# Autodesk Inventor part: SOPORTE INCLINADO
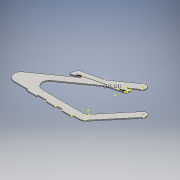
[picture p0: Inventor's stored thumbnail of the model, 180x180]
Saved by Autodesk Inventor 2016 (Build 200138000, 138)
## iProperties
Created: 2016-06
Part Number: SOPORTE INCLINADO
Material: Genérico
Document SubType Name: Modeling
Designer: adm
Density: 1 g/cm^3
Appearance: Valor por defecto
Author: adm
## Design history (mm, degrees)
sketch "Boceto1"
  geometry: L1 (45.284, -220.263)-(201.715, -33.835); L2 (26.631, -180.263)-(171.073, -8.123); L3 (3.65, -190.979)-(-234.496, -190.979); L4 (55.109, 102.688)-(-257.583, -118.314); L5 (32.022, 135.353)-(-383.482, -158.314); L6 (-269.73, -230.979)-(-269.73, -233.979); L7 (-229.73, -230.979)-(-229.73, -233.979); L8 (-159.73, -230.979)-(-159.73, -233.979); L9 (-119.73, -230.979)-(-119.73, -233.979); L10 (-49.73, -230.979)-(-49.73, -233.979); L11 (-40.276, -230.979)-(-40.276, -233.979); L12 (-49.73, -233.979)-(-40.276, -233.979); L13 (-269.73, -233.979)-(-229.73, -233.979); L14 (-159.73, -233.979)-(-119.73, -233.979); L15 (22.302, -230.979)-(-40.276, -230.979); L16 (-49.73, -230.979)-(-119.73, -230.979); L17 (-159.73, -230.979)-(-229.73, -230.979); L18 (-269.73, -230.979)-(-360.395, -230.979); C1 r 3.25 at (186.394, -20.979); C2 r 3.25 at (43.566, 119.021); A1 r 30 centre (22.302, -200.979) between (22.302, -230.979) and (45.284, -220.263); A2 r 20 centre (186.394, -20.979) between (201.715, -33.835) and (171.073, -8.123); A3 r 30 centre (3.65, -160.979) between (3.65, -190.979) and (26.631, -180.263); A4 r 20 centre (43.566, 119.021) between (55.109, 102.688) and (32.022, 135.353); A5 r 40 centre (-234.496, -150.979) between (-257.583, -118.314) and (-234.496, -190.979); A6 r 40 centre (-360.395, -190.979) between (-383.482, -158.314) and (-360.395, -230.979); 3 further points
  constraints: 36 end point, 15 tangent, 13 point on circle, 8 centre point, 3 coincident, 3 horizontal, 3 horizontal alignment, 1 point on line
  dimensions: "d3" = 40 radius of A6; "d5" = 40 radius of A5; "d6" = 30 radius of A3; "d7" = 30 radius of A1; "d20" = 6.5 diameter of C2; "d21" = 6.5 diameter of C1; "d38" = 210 distance from line of C1.centre L15; "d39" = 40 distance between parallel lines of L16 L3; "d40" = 40 distance between parallel lines of L2 L1; "d41" = 40 distance between parallel lines of L5 L4; "d42" = 62.57873 distance of L15.start L11.start; "d43" = 3 distance of L10.start L10.end; "d44" = 3 distance of L11.start L11.end; "d45" = 238.14615 distance of L3.start L3.end; "d46" = 20 radius of A2; "d47" = 350 distance from line of C2.centre L16; "d48" = 20 radius of A4; "d49" = 130 deg angle of L3 L2; "d51" = 200 distance of A4.centre C1.centre
extrude "Extrusión1" new body sketch "Boceto1" distance "d18" = 6; taper "d19" = 0 deg
sketch "Boceto4" dims "d92" = 86
  geometry: L1 (-201.715, -33.835)-(-45.284, -220.263) reference; L2 (-22.302, -230.979)-(40.276, -230.979) reference; L3 (40.276, -230.979)-(40.276, -233.979) reference; L4 (40.276, -233.979)-(49.73, -233.979) reference; L5 (49.73, -233.979)-(49.73, -230.979) reference; L6 (49.73, -230.979)-(119.73, -230.979) reference; L7 (119.73, -230.979)-(119.73, -233.979) reference; L8 (119.73, -233.979)-(159.73, -233.979) reference; L9 (159.73, -233.979)-(159.73, -230.979) reference; L10 (159.73, -230.979)-(229.73, -230.979) reference; L11 (229.73, -230.979)-(229.73, -233.979) reference; L12 (229.73, -233.979)-(269.73, -233.979) reference; L13 (269.73, -233.979)-(269.73, -230.979) reference; L14 (269.73, -230.979)-(360.395, -230.979) reference; L15 (383.482, -158.314)-(-32.022, 135.353) reference; L16 (-55.109, 102.688)-(257.583, -118.314) reference; L17 (234.496, -190.979)-(-3.65, -190.979) reference; L18 (-26.631, -180.263)-(-171.073, -8.123) reference; L19 (-43.566, 119.021)-(-186.394, -20.979); L20 (-13.466, 88.313)-(-115.139, -11.347); L21 (-27.743, 64.115)-(-26.532, 42.84); L22 (-22.812, 38.289)-(233.224, -29.065); L23 (239.266, -22.731)-(228.5, 11.547); L24 (-16.933, 39.845)-(10.145, 32.721); L25 (10.145, 32.721)-(11.724, 38.721); L26 (11.724, 38.721)-(-15.355, 45.845); L27 (-15.355, 45.845)-(-16.933, 39.845); L28 (183.373, -12.849)-(210.451, -19.972); L29 (210.451, -19.972)-(211.978, -14.169); L30 (211.978, -14.169)-(184.899, -7.046); L31 (184.899, -7.046)-(183.373, -12.849); L32 (-22.169, 69.365)-(226.174, 14.411); C1 r 3.25 at (-43.566, 119.021); C2 r 8 at (-43.566, 119.021); C3 r 3.25 at (-43.566, 119.021); C4 r 3.25 at (-43.566, 119.021) reference; C5 r 3.25 at (-186.394, -20.979) reference; C6 r 3.25 at (-43.566, 119.021) reference; C7 r 3.25 at (-186.394, -20.979) reference; A1 r 20 centre (-43.566, 119.021) between (-32.022, 102.688) and (-55.109, 135.353); A2 r 30 centre (-22.302, -200.979) between (-45.284, -220.263) and (-22.302, -230.979) reference; A3 r 40 centre (360.395, -190.979) between (360.395, -230.979) and (383.482, -158.314) reference; A4 r 20 centre (-43.566, 119.021) between (-32.022, 135.353) and (-55.109, 102.688) reference; A5 r 40 centre (234.496, -150.979) between (234.496, -190.979) and (257.583, -118.314) reference; A6 r 30 centre (-3.65, -160.979) between (-26.631, -180.263) and (-3.65, -190.979) reference; A7 r 20 centre (-186.394, -20.979) between (-171.073, -8.123) and (-201.715, -33.835) reference; A8 r 5 centre (-22.751, 64.399) between (-22.169, 69.365) and (-27.743, 64.115); A9 r 5 centre (-21.54, 43.125) between (-26.532, 42.84) and (-22.812, 38.289); A10 r 5 centre (234.496, -24.229) between (233.224, -29.065) and (239.266, -22.731); A11 r 5 centre (223.73, 10.049) between (228.5, 11.547) and (226.174, 14.411); 3 further points
  constraints: 28 end point, 10 point on circle, 8 centre point, 6 tangent, 5 coincident, 5 parallel, 3 equal radius, 2 perpendicular, 4 other
  dimensions: "d91" = 16 diameter of C2; "d112" = 57.8254 deg angle of L22 L23; "d113" = 90 deg angle of L25 L24; "d114" = 6 vertical distance of L26.end L24.start; "d115" = 90 deg angle of L28 L31; "d116" = 6 distance of L30.end L28.start; "d118" = 28 distance of L29.end L30.end; "d119" = 28 distance of L25.end L26.end; "d120" = 3 distance between parallel lines of L22 L28; "d121" = 3 distance between parallel lines of L22 L24; "d122" = 5 radius of A8
extrude "Extrusión4" join sketch "Boceto4" distance "d123" = 6; taper "d124" = 0 deg
sketch "Boceto5"
  geometry: L1 (40.276, -230.979)-(-22.302, -230.979) reference; L2 (15.003, -230.979)-(75.003, -230.979); L3 (75.003, -230.979)-(75.003, -238.979); L4 (75.003, -238.979)-(15.003, -238.979); L5 (15.003, -238.979)-(15.003, -230.979); L6 (109.73, -230.979)-(169.73, -230.979); L7 (169.73, -230.979)-(169.73, -238.979); L8 (169.73, -238.979)-(109.73, -238.979); L9 (109.73, -238.979)-(109.73, -230.979); L10 (229.73, -230.979)-(159.73, -230.979) reference; L11 (219.73, -230.979)-(279.73, -230.979); L12 (279.73, -230.979)-(279.73, -238.979); L13 (279.73, -238.979)-(219.73, -238.979); L14 (219.73, -238.979)-(219.73, -230.979); L15 (229.73, -233.979)-(269.73, -233.979) reference; L16 (119.73, -233.979)-(159.73, -233.979) reference; L17 (40.276, -233.979)-(49.73, -233.979) reference; 7 further points
  constraints: 24 end point, 6 midpoint, 6 parallel, 3 horizontal, 3 perpendicular, 3 vertical alignment, 2 point on line, 1 horizontal alignment
  dimensions: "d125" = 8 distance of L2.end L3.end; "d126" = 8 distance of L6.end L7.end; "d127" = 8 distance of L11.end L12.end; "d128" = 60 distance of L3.end L4.end; "d129" = 60 distance of L7.end L8.end; "d130" = 60 distance of L12.end L13.end
extrude "Extrusión5" join sketch "Boceto5" distance "d131" = 6; taper "d132" = 0 deg
sketch "Boceto6"
  geometry: L1 (-16.933, 39.845)-(-15.355, 45.845) reference; L2 (211.978, -14.169)-(210.451, -19.972) reference; L3 (11.724, 38.721)-(10.145, 32.721) reference; 1 further point
  dimensions: "d133" = 235.12109 distance between parallel lines of L1 L2 (derived)
sketch "Boceto7"
  geometry: 30 further points
node "Sólido1"
node "Contorno proyectado2"
other parameters: "d4" = 50 deg, "d11" = 3, "d23" = 3, "d33" = 3, "d34" = 2
